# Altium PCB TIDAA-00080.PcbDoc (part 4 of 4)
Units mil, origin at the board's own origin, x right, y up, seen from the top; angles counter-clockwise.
Board outline 7874.02 x 2559.06 mil, 4 copper layers (Top Layer, MidLayer1, MidLayer2, Bottom Layer), stack 61.2 mil thick; 363 components, 169 nets, 940 pads, 199 vias.
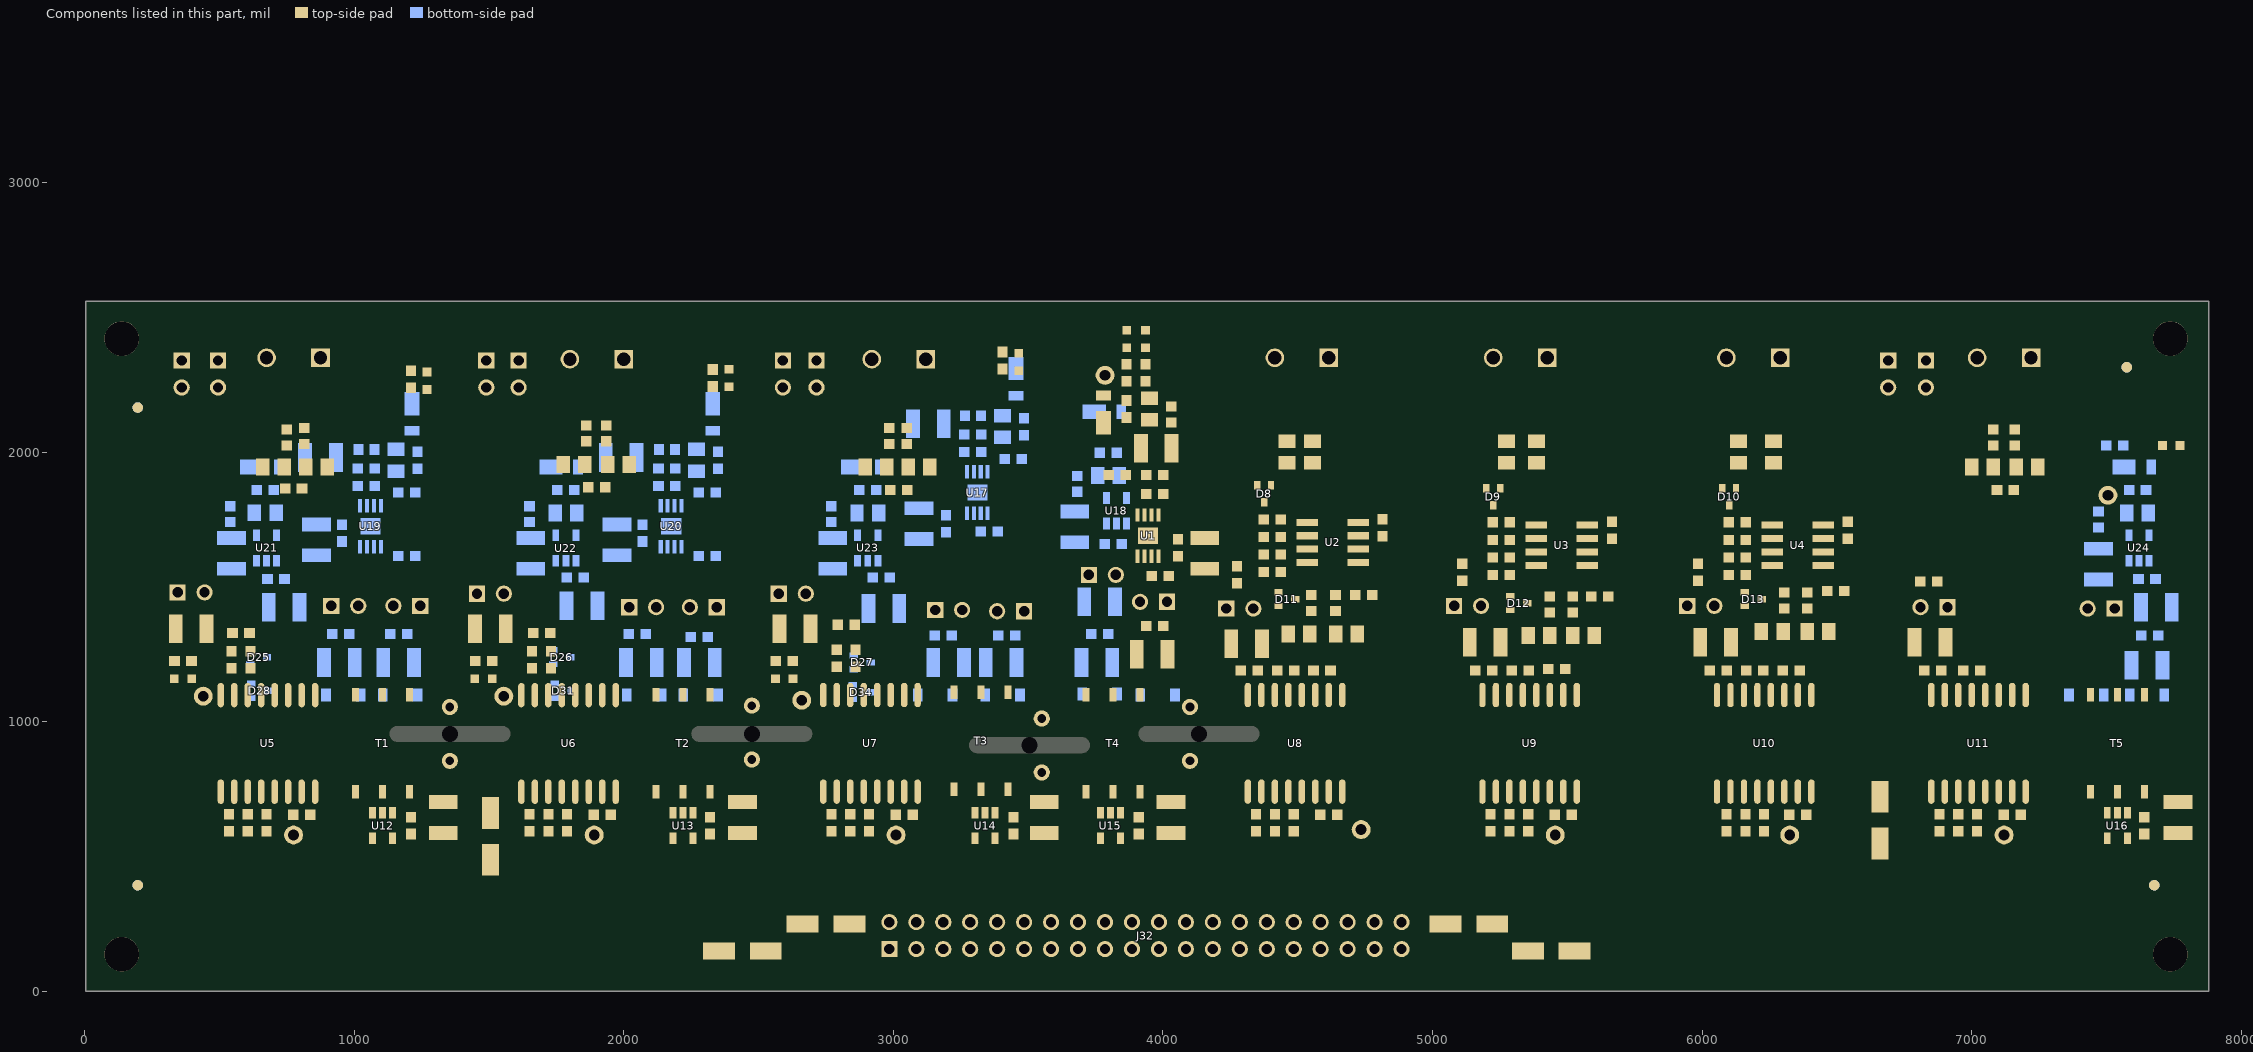
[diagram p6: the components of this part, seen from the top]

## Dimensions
7736.22,2421.26 to 7874.02,2559.06 on M2 Board Dimensions
7736.22,2421.26 to 7874.02,2559.06 on M2 Board Dimensions
0,2559.06 to 7874.02,2559.06 on Drill Drawing
0,0 to 5,2559.06 on Drill Drawing
7736.22,2421.26 to 7736.22,137.8 on M2 Board Dimensions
